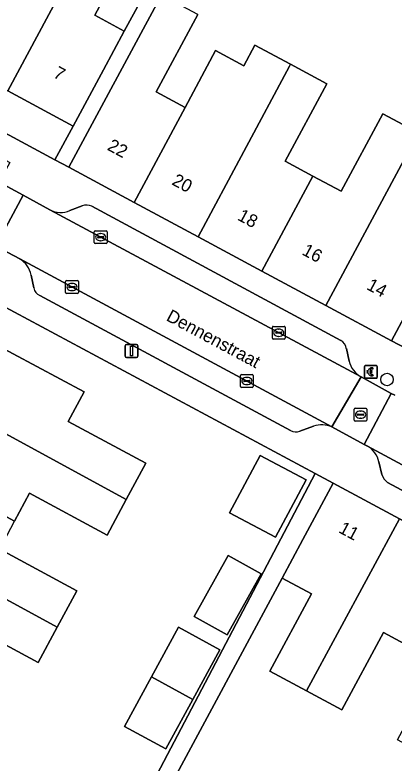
# Model space of a CAD drawing. Extents: x 159262 to 160143, y 383399 to 384319.
# Drawn here: x 159859.4 to 159889, y 383816.3 to 383874.8 of the extents above; entities that cross this region are included whole.
import ezdxf

# ---------------------------------------------------------------- set-up
doc = ezdxf.new("R2010")
doc.units = 0
for name, color, linetype in [('IMGEO_Betaalautomaat', 7, 'Continuous'), ('IMGEO_Boom', 7, 'Continuous'), ('IMGEO_Erf', 7, 'Continuous'), ('IMGEO_Kolk', 7, 'Continuous'), ('IMGEO_Lichtmast', 7, 'Continuous'), ('IMGEO_Openbare_ruimte_label', 7, 'Continuous'), ('IMGEO_Pand', 7, 'Continuous'), ('IMGEO_Pand_nummerreeks', 7, 'Continuous'), ('IMGEO_Parkeervlak_open', 7, 'Continuous'), ('IMGEO_Rijbaan_lokaal_open', 7, 'Continuous'), ('IMGEO_Rioolput', 7, 'Continuous'), ('IMGEO_Voetpad_open', 7, 'Continuous')]:
    doc.layers.add(name, color=color, linetype=linetype)

msp = doc.modelspace()

# ---------------------------------------------------------------- linework, layer by layer
at = {"layer": 'IMGEO_Betaalautomaat'}
for p, q in [((159886.689, 383846.501), (159886.689, 383847.342)), ((159886.689, 383847.342), (159886.689, 383846.501)), ((159886.764, 383847.425), (159887.605, 383847.425)), ((159887.605, 383847.425), (159886.764, 383847.425)), ((159887.351, 383847.23), (159887.334, 383847.13)), ((159887.688, 383847.351), (159887.688, 383846.51)), ((159887.688, 383846.51), (159887.688, 383847.351)), ((159886.972, 383846.889), (159886.972, 383846.957)), ((159887.093, 383846.957), (159887.093, 383846.889)), ((159887.338, 383846.724), (159887.36, 383846.637)), ((159887.614, 383846.426), (159886.773, 383846.426)), ((159886.773, 383846.426), (159887.614, 383846.426))]:
    msp.add_line(p, q, dxfattribs=at)
for points in [[(159886.972, 383846.957), (159886.903, 383846.957), (159886.903, 383847.026), (159886.982, 383847.026)], [(159886.977, 383846.82), (159886.903, 383846.82), (159886.903, 383846.889), (159886.972, 383846.889)], [(159887.104, 383847.026), (159887.251, 383847.026), (159887.251, 383846.957), (159887.093, 383846.957)], [(159887.093, 383846.889), (159887.251, 383846.889), (159887.251, 383846.82), (159887.107, 383846.82)]]:
    msp.add_lwpolyline(points, dxfattribs=at)
for centre, radius, start, end in [((159886.767, 383847.348), 0.0779, 92.4484, 184.28452), ((159886.767, 383847.348), 0.0779, 92.4484, 184.28452), ((159887.265, 383846.95), 0.293, 73.01398, 165.01395), ((159887.271, 383846.963), 0.179, 69.32359, 159.56827), ((159887.611, 383847.348), 0.0779, 2.4484, 94.28452), ((159887.611, 383847.348), 0.0779, 2.4484, 94.28452), ((159886.767, 383846.504), 0.0779, 182.4484, 274.28452), ((159886.767, 383846.504), 0.0779, 182.4484, 274.28452), ((159887.238, 383846.875), 0.267, 191.80956, 297.03891), ((159887.271, 383846.89), 0.179, 202.76249, 291.86925), ((159887.611, 383846.504), 0.0779, 272.4484, 4.28452), ((159887.611, 383846.504), 0.0779, 272.4484, 4.28452)]:
    msp.add_arc(centre, radius, start, end, dxfattribs=at)
at = {"layer": 'IMGEO_Boom'}
msp.add_circle((159888.448, 383846.328), 0.489, dxfattribs=at)
at = {"layer": 'IMGEO_Erf'}
for points in [[(159857.814, 383879.021), (159859.986, 383877.851), (159863.241, 383883.9), (159866.027, 383882.401), (159868.868, 383880.871), (159865.612, 383874.821), (159867.913, 383873.583), (159878.358, 383892.676), (159879.774, 383895.188), (159877.476, 383896.498), (159876.372, 383894.538), (159873.332, 383896.252), (159870.579, 383897.803), (159871.677, 383899.751), (159860.69, 383905.944), (159850.802, 383903.112)], [(159873.658, 383874.885), (159870.402, 383868.825), (159872.661, 383867.612), (159875.042, 383872.055), (159877.256, 383870.868), (159878.125, 383872.486), (159880.905, 383870.991), (159883.745, 383869.465), (159880.489, 383863.405), (159882.654, 383862.242), (159884.857, 383861.057), (159888.114, 383867.117), (159890.899, 383865.62), (159893.743, 383864.092), (159890.486, 383858.032), (159892.79, 383856.809), (159904.193, 383877.652)], [(159843.313, 383873.858), (159862.494, 383863.516), (159863.919, 383866.158), (159858.802, 383868.911)], [(159857.358, 383849.341), (159864.778, 383845.357), (159863.539, 383843.041), (159869.595, 383839.774), (159868.067, 383836.942), (159867.221, 383835.374), (159866.566, 383834.16), (159860.511, 383837.428), (159859.328, 383835.235)], [(159858.155, 383833.062), (159864.209, 383829.794), (159862.677, 383826.956), (159861.179, 383824.178), (159855.124, 383827.446)], [(159899.258, 383812.769), (159902.516, 383818.828), (159900.471, 383819.928), (159898.165, 383821.167), (159894.908, 383815.108), (159892.192, 383816.567), (159889.272, 383818.138), (159892.53, 383824.197), (159890.438, 383825.321), (159888.163, 383826.545), (159884.905, 383820.486), (159882.159, 383821.962), (159879.293, 383823.502), (159882.545, 383829.552), (159880.248, 383830.787), (159871.294, 383814.131)]]:
    msp.add_lwpolyline(points, dxfattribs=at)
for points in [[(159882.827, 383838.967), (159856.103, 383853.317), (159839.043, 383821.661), (159826.175, 383818.139), (159825.07, 383817.837), (159832.903, 383788.947), (159833.158, 383789.017), (159832.573, 383791.181), (159835.671, 383792.017), (159836.255, 383789.853), (159836.757, 383789.988), (159835.835, 383793.404), (159840.442, 383794.663), (159840.765, 383793.48), (159846.59, 383795.072), (159847.208, 383792.81), (159859.628, 383796.267), (159860.523, 383796.509)], [(159876.134, 383835.891), (159878.521, 383840.391), (159882.117, 383838.483), (159879.731, 383833.983)], [(159876.025, 383832.554), (159878.604, 383831.114), (159875.943, 383826.351), (159873.364, 383827.792)], [(159870.031, 383823.067), (159872.151, 383826.957), (159875.387, 383825.194), (159873.269, 383821.306), (159871.157, 383817.429), (159867.92, 383819.193)]]:
    msp.add_lwpolyline(points, close=True, dxfattribs=at)
at = {"layer": 'IMGEO_Kolk'}
for p, q in [((159865.568, 383857.037), (159865.568, 383857.889)), ((159865.643, 383857.963), (159866.495, 383857.963)), ((159866.056, 383857.743), (159866.081, 383857.743)), ((159866.569, 383857.889), (159866.569, 383857.037)), ((159865.827, 383857.457), (159865.827, 383857.469)), ((159866.265, 383857.42), (159865.867, 383857.42)), ((159865.87, 383857.506), (159866.268, 383857.506)), ((159866.079, 383857.183), (159866.054, 383857.183)), ((159866.311, 383857.469), (159866.311, 383857.457)), ((159866.495, 383856.963), (159865.643, 383856.963)), ((159863.398, 383854.067), (159864.25, 383854.067)), ((159863.323, 383853.141), (159863.323, 383853.993)), ((159863.582, 383853.561), (159863.582, 383853.573)), ((159864.02, 383853.524), (159863.622, 383853.524)), ((159863.625, 383853.61), (159864.023, 383853.61)), ((159863.811, 383853.847), (159863.836, 383853.847)), ((159864.066, 383853.573), (159864.066, 383853.561)), ((159864.324, 383853.993), (159864.324, 383853.141)), ((159864.25, 383853.067), (159863.398, 383853.067)), ((159863.834, 383853.287), (159863.809, 383853.287)), ((159879.486, 383849.559), (159879.486, 383850.411)), ((159879.561, 383850.485), (159880.413, 383850.485)), ((159879.745, 383849.979), (159879.745, 383849.991)), ((159879.788, 383850.028), (159880.186, 383850.028)), ((159879.974, 383850.265), (159879.999, 383850.265)), ((159880.229, 383849.991), (159880.229, 383849.979)), ((159880.487, 383850.411), (159880.487, 383849.559)), ((159880.413, 383849.485), (159879.561, 383849.485)), ((159880.183, 383849.942), (159879.785, 383849.942)), ((159879.997, 383849.705), (159879.972, 383849.705)), ((159876.994, 383845.782), (159876.994, 383846.634)), ((159877.069, 383846.708), (159877.921, 383846.708)), ((159877.482, 383846.488), (159877.507, 383846.488)), ((159877.995, 383846.634), (159877.995, 383845.782)), ((159877.253, 383846.202), (159877.253, 383846.214)), ((159877.691, 383846.165), (159877.293, 383846.165)), ((159877.296, 383846.251), (159877.694, 383846.251)), ((159877.505, 383845.928), (159877.48, 383845.928)), ((159877.737, 383846.214), (159877.737, 383846.202)), ((159877.921, 383845.708), (159877.069, 383845.708))]:
    msp.add_line(p, q, dxfattribs=at)
for points in [[(159865.568, 383857.037), (159865.568, 383857.889)], [(159865.643, 383857.963), (159866.495, 383857.963)], [(159866.569, 383857.889), (159866.569, 383857.037)], [(159866.495, 383856.963), (159865.643, 383856.963)], [(159863.398, 383854.067), (159864.25, 383854.067)], [(159863.323, 383853.141), (159863.323, 383853.993)], [(159864.324, 383853.993), (159864.324, 383853.141)], [(159864.25, 383853.067), (159863.398, 383853.067)], [(159879.486, 383849.559), (159879.486, 383850.411)], [(159879.561, 383850.485), (159880.413, 383850.485)], [(159880.487, 383850.411), (159880.487, 383849.559)], [(159880.413, 383849.485), (159879.561, 383849.485)], [(159876.994, 383845.782), (159876.994, 383846.634)], [(159877.069, 383846.708), (159877.921, 383846.708)], [(159877.995, 383846.634), (159877.995, 383845.782)], [(159877.921, 383845.708), (159877.069, 383845.708)]]:
    msp.add_lwpolyline(points, dxfattribs=at)
for centre, radius, start, end in [((159865.645, 383857.887), 0.0765, 91.55205, 178.44795), ((159865.645, 383857.887), 0.0765, 91.55205, 178.44795), ((159866.493, 383857.887), 0.0765, 1.55205, 88.44795), ((159866.493, 383857.887), 0.0765, 1.55205, 88.44795), ((159865.645, 383857.039), 0.0765, 181.55205, 268.44795), ((159865.645, 383857.039), 0.0765, 181.55205, 268.44795), ((159865.867, 383857.466), 0.0403, 85.87752, 175.75265), ((159865.864, 383857.456), 0.0366, 178.93798, 274.71019), ((159866.268, 383857.463), 0.043, 264.86636, 352.45326), ((159866.272, 383857.468), 0.0386, 1.73085, 96.63898), ((159866.493, 383857.039), 0.0765, 271.55205, 358.44795), ((159866.493, 383857.039), 0.0765, 271.55205, 358.44795), ((159863.4, 383853.991), 0.0765, 91.55205, 178.44795), ((159863.4, 383853.991), 0.0765, 91.55205, 178.44795), ((159864.248, 383853.991), 0.0765, 1.55205, 88.44795), ((159864.248, 383853.991), 0.0765, 1.55205, 88.44795), ((159863.622, 383853.57), 0.0403, 85.87752, 175.75265), ((159863.619, 383853.56), 0.0366, 178.93798, 274.71019), ((159864.023, 383853.567), 0.043, 264.86636, 352.45326), ((159864.027, 383853.572), 0.0386, 1.73085, 96.63898), ((159863.4, 383853.143), 0.0765, 181.55205, 268.44795), ((159863.4, 383853.143), 0.0765, 181.55205, 268.44795), ((159864.248, 383853.143), 0.0765, 271.55205, 358.44795), ((159864.248, 383853.143), 0.0765, 271.55205, 358.44795), ((159879.563, 383850.409), 0.0765, 91.55205, 178.44795), ((159879.563, 383850.409), 0.0765, 91.55205, 178.44795), ((159879.785, 383849.988), 0.0403, 85.87752, 175.75265), ((159879.782, 383849.978), 0.0366, 178.93798, 274.71019), ((159880.186, 383849.985), 0.043, 264.86636, 352.45326), ((159880.19, 383849.99), 0.0386, 1.73085, 96.63898), ((159880.411, 383850.409), 0.0765, 1.55205, 88.44795), ((159880.411, 383850.409), 0.0765, 1.55205, 88.44795), ((159879.563, 383849.561), 0.0765, 181.55205, 268.44795), ((159879.563, 383849.561), 0.0765, 181.55205, 268.44795), ((159880.411, 383849.561), 0.0765, 271.55205, 358.44795), ((159880.411, 383849.561), 0.0765, 271.55205, 358.44795), ((159877.071, 383846.632), 0.0765, 91.55205, 178.44795), ((159877.071, 383846.632), 0.0765, 91.55205, 178.44795), ((159877.919, 383846.632), 0.0765, 1.55205, 88.44795), ((159877.919, 383846.632), 0.0765, 1.55205, 88.44795), ((159877.293, 383846.211), 0.0403, 85.87752, 175.75265), ((159877.29, 383846.201), 0.0366, 178.93798, 274.71019), ((159877.694, 383846.208), 0.043, 264.86636, 352.45326), ((159877.698, 383846.213), 0.0386, 1.73085, 96.63898), ((159877.071, 383845.784), 0.0765, 181.55205, 268.44795), ((159877.071, 383845.784), 0.0765, 181.55205, 268.44795), ((159877.919, 383845.784), 0.0765, 271.55205, 358.44795), ((159877.919, 383845.784), 0.0765, 271.55205, 358.44795)]:
    msp.add_arc(centre, radius, start, end, dxfattribs=at)
for centre, major_axis, ratio, start_param, end_param in [((159866.055, 383857.463), (-0.387, 0.002), 0.722429, 4.712389, 7.853982), ((159866.08, 383857.463), (-0.39, 0.002), 0.717154, 1.570796, 4.712389), ((159863.81, 383853.567), (-0.387, 0.002), 0.722429, 4.712389, 7.853982), ((159863.835, 383853.567), (-0.39, 0.002), 0.717154, 1.570796, 4.712389), ((159879.973, 383849.985), (-0.387, 0.002), 0.722429, 4.712389, 7.853982), ((159879.998, 383849.985), (-0.39, 0.002), 0.717154, 1.570796, 4.712389), ((159877.481, 383846.208), (-0.387, 0.002), 0.722429, 4.712389, 7.853982), ((159877.506, 383846.208), (-0.39, 0.002), 0.717154, 1.570796, 4.712389)]:
    msp.add_ellipse(centre, major_axis=major_axis, ratio=ratio, start_param=start_param, end_param=end_param, dxfattribs=at)
at = {"layer": 'IMGEO_Lichtmast'}
for p, q in [((159867.974, 383848.16), (159867.974, 383848.96)), ((159867.974, 383848.96), (159867.974, 383848.16)), ((159868.074, 383849.06), (159868.864, 383849.06)), ((159868.864, 383849.06), (159868.074, 383849.06)), ((159868.964, 383848.96), (159868.964, 383848.16)), ((159868.964, 383848.16), (159868.964, 383848.96)), ((159868.864, 383848.06), (159868.074, 383848.06)), ((159868.074, 383848.06), (159868.864, 383848.06))]:
    msp.add_line(p, q, dxfattribs=at)
msp.add_lwpolyline([(159868.394, 383848.935), (159868.544, 383848.935), (159868.544, 383848.185), (159868.394, 383848.185), (159868.394, 383848.935)], dxfattribs=at)
for centre, start, end in [((159868.074, 383848.96), 90, 180), ((159868.074, 383848.96), 90, 180), ((159868.864, 383848.96), 0, 90), ((159868.864, 383848.96), 360, 90), ((159868.074, 383848.16), 180, 270), ((159868.074, 383848.16), 180, 270), ((159868.864, 383848.16), 270, 0), ((159868.864, 383848.16), 270, 0)]:
    msp.add_arc(centre, 0.1, start, end, dxfattribs=at)
at = {"layer": 'IMGEO_Pand'}
for points in [[(159865.965, 383882.285), (159866.027, 383882.401), (159863.241, 383883.9), (159859.986, 383877.851), (159857.814, 383879.021), (159853.831, 383871.586), (159858.802, 383868.911)], [(159865.612, 383874.821), (159868.868, 383880.871), (159866.027, 383882.401), (159865.965, 383882.285), (159858.802, 383868.911), (159863.919, 383866.158), (159866.288, 383870.562), (159867.913, 383873.583)], [(159870.402, 383868.825), (159873.658, 383874.885), (159870.821, 383876.41), (159865.944, 383867.338), (159863.575, 383862.933), (159868.682, 383860.186), (159872.661, 383867.612)], [(159880.822, 383870.835), (159880.905, 383870.991), (159878.125, 383872.486), (159877.256, 383870.868), (159875.042, 383872.055), (159872.661, 383867.612), (159868.682, 383860.186), (159873.678, 383857.5)], [(159880.489, 383863.405), (159883.745, 383869.465), (159880.905, 383870.991), (159880.822, 383870.835), (159873.678, 383857.5), (159878.674, 383854.813), (159882.654, 383862.242)], [(159890.899, 383865.62), (159888.114, 383867.117), (159884.857, 383861.057), (159882.654, 383862.242), (159878.674, 383854.813), (159883.67, 383852.127)], [(159890.486, 383858.032), (159893.743, 383864.092), (159890.899, 383865.62), (159883.67, 383852.127), (159888.807, 383849.364), (159891.161, 383853.78), (159892.79, 383856.809)], [(159863.539, 383843.041), (159864.778, 383845.357), (159857.358, 383849.341), (159854.615, 383844.258), (159868.067, 383836.942), (159869.595, 383839.774)], [(159854.615, 383844.258), (159851.921, 383839.265), (159859.328, 383835.235), (159860.511, 383837.428), (159866.566, 383834.16), (159867.221, 383835.374), (159868.067, 383836.942)], [(159876.134, 383835.891), (159879.731, 383833.983), (159882.117, 383838.483), (159878.521, 383840.391)], [(159859.328, 383835.235), (159851.921, 383839.265), (159849.227, 383834.272), (159862.677, 383826.956), (159864.209, 383829.794), (159858.155, 383833.062)], [(159889.412, 383835.428), (159884.237, 383838.21), (159881.872, 383833.808), (159880.248, 383830.787), (159882.545, 383829.552), (159879.293, 383823.502), (159882.159, 383821.962)], [(159894.429, 383832.73), (159889.412, 383835.428), (159882.159, 383821.962), (159884.905, 383820.486), (159888.163, 383826.545), (159890.438, 383825.321)], [(159849.227, 383834.272), (159846.533, 383829.279), (159853.939, 383825.25), (159855.124, 383827.446), (159861.179, 383824.178), (159862.677, 383826.956)], [(159878.604, 383831.114), (159876.025, 383832.554), (159873.364, 383827.792), (159875.943, 383826.351)], [(159875.387, 383825.194), (159872.151, 383826.957), (159870.031, 383823.067), (159873.269, 383821.306)], [(159873.269, 383821.306), (159870.031, 383823.067), (159867.92, 383819.193), (159871.157, 383817.429)]]:
    msp.add_lwpolyline(points, close=True, dxfattribs=at)
at = {"layer": 'IMGEO_Parkeervlak_open'}
for points in [[(159862.1, 383859.594), (159886.416, 383846.531)], [(159864.62, 383859.909), (159863.664, 383859.54)], [(159884.848, 383849.386), (159865.379, 383859.88)], [(159884.147, 383842.627), (159859.758, 383855.756)], [(159860.635, 383854.502), (159860.841, 383853.494)], [(159861.311, 383852.89), (159880.902, 383842.331)], [(159885.479, 383847.763), (159885.269, 383848.746)], [(159881.647, 383842.279), (159882.705, 383842.669)], [(159888.497, 383838.27), (159912.378, 383825.451), (159913.206, 383826.962), (159886.911, 383841.123)], [(159887.813, 383839.888), (159888.038, 383838.887)]]:
    msp.add_lwpolyline(points, dxfattribs=at)
for centre, radius, start, end in [((159864.963, 383858.937), 1.03, 66.18386, 109.43993), ((159862.941, 383861.27), 1.875, 243.35265, 292.69244), ((159858.754, 383854.12), 1.919, 11.47474, 58.46022), ((159861.673, 383853.657), 0.848, 191.07353, 244.7027), ((159884.408, 383848.638), 0.867, 7.12708, 59.54776), ((159887.393, 383848.247), 1.974, 194.1765, 240.33324), ((159883.368, 383840.665), 2.111, 68.35062, 108.31271), ((159881.332, 383843.132), 0.909, 241.76699, 290.24763), ((159886.017, 383839.523), 1.833, 11.48709, 60.79903), ((159889.164, 383839.245), 1.182, 197.65908, 235.63368)]:
    msp.add_arc(centre, radius, start, end, dxfattribs=at)
at = {"layer": 'IMGEO_Rijbaan_lokaal_open'}
for points in [[(159860.012, 383860.749), (159858.117, 383861.754), (159856.001, 383857.758), (159857.844, 383856.752)], [(159886.416, 383846.531), (159862.1, 383859.594), (159860.012, 383860.749), (159857.844, 383856.752), (159859.758, 383855.756), (159884.147, 383842.627)], [(159886.675, 383841.252), (159888.78, 383845.246), (159886.416, 383846.531), (159884.147, 383842.627)]]:
    msp.add_lwpolyline(points, close=True, dxfattribs=at)
msp.add_lwpolyline([(159889.056, 383845.096), (159888.78, 383845.246), (159886.675, 383841.252), (159886.911, 383841.123), (159913.206, 383826.962), (159913.325, 383827.179), (159917.827, 383824.801)], dxfattribs=at)
at = {"layer": 'IMGEO_Rioolput'}
for p, q in [((159885.879, 383843.155), (159885.879, 383844.007)), ((159885.954, 383844.081), (159886.806, 383844.081)), ((159886.138, 383843.575), (159886.138, 383843.587)), ((159886.576, 383843.538), (159886.178, 383843.538)), ((159886.181, 383843.624), (159886.579, 383843.624)), ((159886.367, 383843.861), (159886.392, 383843.861)), ((159886.622, 383843.587), (159886.622, 383843.575)), ((159886.88, 383844.007), (159886.88, 383843.155)), ((159886.806, 383843.081), (159885.954, 383843.081)), ((159886.39, 383843.301), (159886.365, 383843.301))]:
    msp.add_line(p, q, dxfattribs=at)
for points in [[(159885.879, 383843.155), (159885.879, 383844.007)], [(159885.954, 383844.081), (159886.806, 383844.081)], [(159886.88, 383844.007), (159886.88, 383843.155)], [(159886.806, 383843.081), (159885.954, 383843.081)]]:
    msp.add_lwpolyline(points, dxfattribs=at)
for centre, radius, start, end in [((159885.956, 383844.005), 0.0765, 91.55205, 178.44795), ((159885.956, 383844.005), 0.0765, 91.55205, 178.44795), ((159886.178, 383843.584), 0.0403, 85.87752, 175.75265), ((159886.175, 383843.574), 0.0366, 178.93798, 274.71019), ((159886.579, 383843.581), 0.043, 264.86636, 352.45326), ((159886.583, 383843.586), 0.0386, 1.73085, 96.63898), ((159886.804, 383844.005), 0.0765, 1.55205, 88.44795), ((159886.804, 383844.005), 0.0765, 1.55205, 88.44795), ((159885.956, 383843.157), 0.0765, 181.55205, 268.44795), ((159885.956, 383843.157), 0.0765, 181.55205, 268.44795), ((159886.804, 383843.157), 0.0765, 271.55205, 358.44795), ((159886.804, 383843.157), 0.0765, 271.55205, 358.44795)]:
    msp.add_arc(centre, radius, start, end, dxfattribs=at)
for centre, major_axis, ratio, start_param, end_param in [((159886.366, 383843.581), (-0.387, 0.002), 0.722429, 4.712389, 7.853982), ((159886.391, 383843.581), (-0.39, 0.002), 0.717154, 1.570796, 4.712389)]:
    msp.add_ellipse(centre, major_axis=major_axis, ratio=ratio, start_param=start_param, end_param=end_param, dxfattribs=at)
at = {"layer": 'IMGEO_Voetpad_open'}
for points in [[(159878.358, 383892.676), (159867.913, 383873.583), (159866.288, 383870.562), (159863.919, 383866.158), (159862.494, 383863.516), (159863.575, 383862.933), (159865.944, 383867.338), (159870.821, 383876.41)], [(159904.193, 383877.652), (159892.79, 383856.809), (159891.161, 383853.78), (159888.807, 383849.364), (159889.903, 383848.788), (159892.268, 383853.189), (159893.897, 383856.219), (159903.366, 383873.832), (159904.81, 383873.116), (159908.492, 383871.141), (159913.494, 383868.458), (159918.504, 383865.771), (159923.027, 383863.346)], [(159900.029, 383843.337), (159895.027, 383846.029), (159889.903, 383848.788), (159888.807, 383849.364), (159883.67, 383852.127), (159878.674, 383854.813), (159873.678, 383857.5), (159868.682, 383860.186), (159863.575, 383862.933), (159862.494, 383863.516), (159843.313, 383873.858), (159823.801, 383868.486), (159825.103, 383863.552), (159825.597, 383863.637), (159825.844, 383862.726), (159827.864, 383863.295), (159826.716, 383867.62), (159842.848, 383872.034), (159858.979, 383863.311), (159858.117, 383861.754), (159860.012, 383860.749), (159862.1, 383859.594)], [(159863.664, 383859.54), (159864.62, 383859.909)], [(159865.379, 383859.88), (159884.848, 383849.386)], [(159859.758, 383855.756), (159857.844, 383856.752), (159856.103, 383853.317), (159882.827, 383838.967), (159884.237, 383838.21), (159889.412, 383835.428), (159894.429, 383832.73), (159899.446, 383830.033), (159904.462, 383827.336), (159909.479, 383824.639), (159914.461, 383821.96), (159917.055, 383820.574), (159917.816, 383822.24), (159912.321, 383825.347), (159912.378, 383825.451), (159888.497, 383838.27)], [(159860.841, 383853.494), (159860.635, 383854.502)], [(159880.902, 383842.331), (159861.311, 383852.89)], [(159885.269, 383848.746), (159885.479, 383847.763)], [(159886.416, 383846.531), (159888.78, 383845.246), (159889.056, 383845.096)], [(159882.705, 383842.669), (159881.647, 383842.279)], [(159886.911, 383841.123), (159886.675, 383841.252), (159884.147, 383842.627)], [(159888.038, 383838.887), (159887.813, 383839.888)], [(159871.294, 383814.131), (159880.248, 383830.787), (159881.872, 383833.808), (159884.237, 383838.21), (159882.827, 383838.967), (159860.523, 383796.509)]]:
    msp.add_lwpolyline(points, dxfattribs=at)
for centre, radius, start, end in [((159864.963, 383858.937), 1.03, 66.18386, 109.43993), ((159862.941, 383861.27), 1.875, 243.35265, 292.69244), ((159858.754, 383854.12), 1.919, 11.47474, 58.46022), ((159861.673, 383853.657), 0.848, 191.07353, 244.7027), ((159884.408, 383848.638), 0.867, 7.12708, 59.54776), ((159887.393, 383848.247), 1.974, 194.1765, 240.33324), ((159883.368, 383840.665), 2.111, 68.35062, 108.31271), ((159881.332, 383843.132), 0.909, 241.76699, 290.24763), ((159886.017, 383839.523), 1.833, 11.48709, 60.79903), ((159889.164, 383839.245), 1.182, 197.65908, 235.63368)]:
    msp.add_arc(centre, radius, start, end, dxfattribs=at)

# ---------------------------------------------------------------- texts
at = {"layer": 'IMGEO_Openbare_ruimte_label'}
msp.add_text('Dennenstraat', height=1, rotation=331.7691, dxfattribs=at).set_placement((159871.121, 383850.986))
at = {"layer": 'IMGEO_Pand_nummerreeks'}
for s, rotation, p in [('7', 331.70161, (159862.292, 383870.011)), ('22', 331.71307, (159866.514, 383864.329)), ('20', 331.71307, (159871.564, 383861.611)), ('18', 331.71307, (159876.69, 383858.853)), ('16', 331.71307, (159881.733, 383856.139)), ('14', 331.71307, (159886.779, 383853.424)), ('11', 331.73026, (159884.597, 383834.399))]:
    msp.add_text(s, height=1, rotation=rotation, dxfattribs=at).set_placement(p)

doc.saveas('drawing.dxf')
